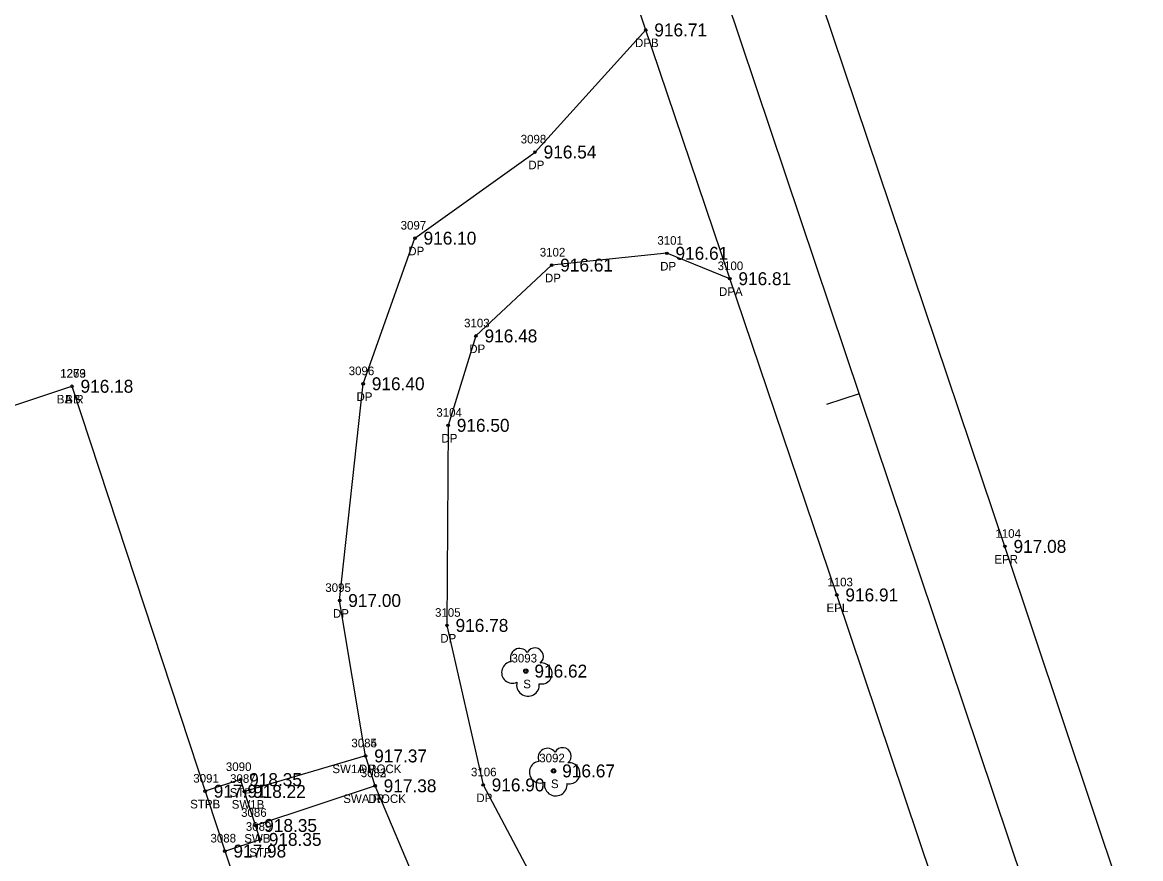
# Model space of a CAD drawing. Extents: x 1528109 to 1531398, y 1157799 to 1162548.
# Drawn here: x 1529705.3 to 1529835.3, y 1159763.8 to 1159860.9 of the extents above; entities that cross this region are included whole.
import ezdxf

# ---------------------------------------------------------------- set-up
doc = ezdxf.new("R2010")
doc.units = 0
for name, color, linetype in [('RD_EX_Bldg', 7, 'Continuous'), ('RD_EX_Bldg_txCode', 7, 'Continuous'), ('RD_EX_Conc', 7, 'Continuous'), ('RD_EX_Conc_txCode', 7, 'Continuous'), ('RD_EX_Driveway', 7, 'Continuous'), ('RD_EX_Driveway_txCode', 7, 'Continuous'), ('RD_EX_Road', 7, 'Continuous'), ('RD_EX_Road_txCode', 7, 'Continuous'), ('RD_EX_TX_Bldg_ELEV', 7, 'Continuous'), ('RD_EX_TX_Conc_ELEV', 7, 'Continuous'), ('RD_EX_TX_Driveway_ELEV', 7, 'Continuous'), ('RD_EX_TX_Road_ELEV', 7, 'Continuous'), ('RD_EX_TX_VEG_ELEV', 7, 'Continuous'), ('RD_EX_VEG', 7, 'Continuous'), ('RD_EX_VEG_txCode', 7, 'Continuous'), ('RD_HC_Cl', 7, 'Continuous'), ('RD_HC_Data_Tic', 7, 'Continuous'), ('RD_SMD_Locator', 7, 'Continuous')]:
    doc.layers.add(name, color=color, linetype=linetype)

msp = doc.modelspace()

# ---------------------------------------------------------------- linework, layer by layer
at = {"layer": 'RD_EX_Bldg'}
msp.add_lwpolyline([(1529711.08, 1159818.65), (1529739.39, 1159732.67), (1529692.67, 1159717.1), (1529664.36, 1159803.09), (1529711.08, 1159818.65)], dxfattribs=at)
at = {"layer": 'RD_EX_Conc'}
for p, q in [((1529745.23, 1159775.69), (1529731.14, 1159771.56)), ((1529746.33, 1159772.22), (1529732.44, 1159767.61))]:
    msp.add_line(p, q, dxfattribs=at)
msp.add_lwpolyline([(1529728.86, 1159764.63), (1529732.97, 1159765.99), (1529730.69, 1159772.94), (1529726.57, 1159771.59)], dxfattribs=at)
at = {"layer": 'RD_EX_Driveway'}
for points in [[(1529735.42, 1159713.63), (1529749.47, 1159720.19), (1529757.11, 1159728.54), (1529760.1, 1159739.68), (1529746.33, 1159772.22), (1529745.23, 1159775.69), (1529742.21, 1159793.75), (1529744.95, 1159818.94), (1529750.97, 1159835.86), (1529764.93, 1159845.87), (1529777.8, 1159860.06)], [(1529787.58, 1159831.15), (1529780.26, 1159834.1), (1529766.86, 1159832.73), (1529758.06, 1159824.5), (1529754.83, 1159814.11), (1529754.69, 1159790.86), (1529758.89, 1159772.32), (1529770.42, 1159750.59), (1529785.67, 1159734.66), (1529798.53, 1159731), (1529808.47, 1159733.63), (1529813.75, 1159739.88), (1529816.24, 1159746.21)]]:
    msp.add_lwpolyline(points, dxfattribs=at)
at = {"layer": 'RD_EX_Road'}
for points in [[(1530337.52, 1159156.44), (1530294.13, 1159166.93), (1530250.93, 1159177.7), (1530204.42, 1159191.5), (1530168.45, 1159204.97), (1530120.58, 1159231.54), (1530104.56, 1159243.15), (1530086.77, 1159257.61), (1530051.98, 1159290.88), (1530019.2, 1159326.18), (1529978.15, 1159378.31), (1529959.68, 1159408.2), (1529942.81, 1159442.34), (1529934.79, 1159460.88), (1529923.22, 1159491.09), (1529910.46, 1159527.95), (1529895.99, 1159570.93), (1529881.69, 1159613.98), (1529856.28, 1159690.67), (1529839.74, 1159739.71), (1529819.57, 1159800.04), (1529788.95, 1159890.99)], [(1530332.28, 1159136.67), (1530288.96, 1159147.06), (1530245.68, 1159158), (1530197.52, 1159172.18), (1530159.1, 1159186.57), (1530108.6, 1159214.89), (1530072.67, 1159242.37), (1530037.12, 1159276.96), (1530005.21, 1159311.5), (1529961.59, 1159366.88), (1529941.79, 1159398.29), (1529924.06, 1159434.11), (1529903.77, 1159484.39), (1529891.44, 1159520.8), (1529876.79, 1159564.7), (1529862.9, 1159606.82), (1529836.94, 1159684.29), (1529820.66, 1159733.09), (1529800.02, 1159794.4), (1529769.54, 1159884.46)]]:
    msp.add_lwpolyline(points, dxfattribs=at)
at = {"layer": 'RD_EX_VEG'}
for centre in [(1529763.86, 1159785.55), (1529767.09, 1159773.95)]:
    msp.add_circle(centre, 0.25, dxfattribs=at)
for centre, radius, start, end in [((1529763.14, 1159787.1), 1.08, 34.9763, 204.756), ((1529764.91, 1159787.25), 0.995, 308.7626, 152.0467), ((1529762.3, 1159785.39), 1.26, 96.4518, 294.734), ((1529765.7, 1159785.27), 1.22, 256.5667, 98.1046), ((1529764.11, 1159783.95), 1.32, 166.8827, 5.7589), ((1529766.37, 1159775.5), 1.08, 34.9763, 204.756), ((1529768.14, 1159775.66), 0.995, 308.7626, 152.0467), ((1529765.53, 1159773.8), 1.26, 96.4518, 294.734), ((1529768.93, 1159773.67), 1.22, 256.5667, 98.1046), ((1529767.34, 1159772.36), 1.32, 166.8827, 5.7589)]:
    msp.add_arc(centre, radius, start, end, dxfattribs=at)
at = {"layer": 'RD_HC_Cl'}
msp.add_line((1529913.5, 1159487.74), (1529527.85, 1160635.77), dxfattribs=at)
at = {"layer": 'RD_HC_Data_Tic'}
msp.add_line((1529802.62, 1159817.79), (1529798.83, 1159816.52), dxfattribs=at)
at = {"layer": 'RD_SMD_Locator'}
for centre in [(1529777.8, 1159860.06), (1529764.93, 1159845.87), (1529750.97, 1159835.86), (1529780.26, 1159834.1), (1529766.86, 1159832.73), (1529787.58, 1159831.15), (1529758.06, 1159824.5), (1529711.08, 1159818.65), (1529711.08, 1159818.65), (1529744.95, 1159818.94), (1529754.83, 1159814.11), (1529819.57, 1159800.04), (1529742.21, 1159793.75), (1529800.02, 1159794.4), (1529754.69, 1159790.86), (1529763.86, 1159785.55), (1529745.23, 1159775.69), (1529745.23, 1159775.69), (1529730.69, 1159772.94), (1529767.09, 1159773.95), (1529726.57, 1159771.59), (1529731.14, 1159771.56), (1529746.33, 1159772.22), (1529746.33, 1159772.22), (1529758.89, 1159772.32), (1529732.44, 1159767.61), (1529732.97, 1159765.99), (1529728.86, 1159764.63)]:
    msp.add_circle(centre, 0.15, dxfattribs=at)

# ---------------------------------------------------------------- texts
at = {"layer": 'RD_EX_Bldg_txCode'}
for s, p in [('1269', (1529709.71, 1159819.65)), ('1273', (1529709.73, 1159819.65)), ('BA R', (1529709.32, 1159816.65)), ('BB', (1529710.3, 1159816.65))]:
    msp.add_text(s, height=1, dxfattribs=at).set_placement(p)
at = {"layer": 'RD_EX_Conc_txCode'}
for s, p in [('3084', (1529743.57, 1159776.69)), ('3090', (1529728.98, 1159773.94)), ('SW1A ROCK', (1529741.37, 1159773.69)), ('3083', (1529744.66, 1159773.22)), ('3091', (1529725.19, 1159772.59)), ('3087', (1529729.47, 1159772.56)), ('STP', (1529729.42, 1159770.94)), ('STPB', (1529724.83, 1159769.59)), ('SW1B', (1529729.66, 1159769.56)), ('SWA ROCK', (1529742.63, 1159770.22)), ('3086', (1529730.75, 1159768.61)), ('3089', (1529731.3, 1159766.99)), ('3088', (1529727.19, 1159765.63)), ('SWB', (1529731.12, 1159765.61)), ('STP', (1529731.7, 1159763.99))]:
    msp.add_text(s, height=1, dxfattribs=at).set_placement(p)
at = {"layer": 'RD_EX_Driveway_txCode'}
for s, p in [('DPB', (1529776.55, 1159858.06)), ('3098', (1529763.26, 1159846.87)), ('DP', (1529764.15, 1159843.87)), ('3097', (1529749.3, 1159836.86)), ('3101', (1529779.15, 1159835.1)), ('DP', (1529750.19, 1159833.86)), ('3102', (1529765.48, 1159833.73)), ('DP', (1529779.48, 1159832.1)), ('3100', (1529786.16, 1159832.15)), ('DP', (1529766.08, 1159830.73)), ('DPA', (1529786.32, 1159829.15)), ('3103', (1529756.68, 1159825.5)), ('DP', (1529757.28, 1159822.5)), ('3096', (1529743.26, 1159819.94)), ('DP', (1529744.17, 1159816.94)), ('3104', (1529753.45, 1159815.11)), ('DP', (1529754.05, 1159812.11)), ('3095', (1529740.54, 1159794.75)), ('DP', (1529741.43, 1159791.75)), ('3105', (1529753.3, 1159791.86)), ('DP', (1529753.91, 1159788.86)), ('3085', (1529743.57, 1159776.69)), ('DP', (1529744.45, 1159773.69)), ('3082', (1529744.66, 1159773.22)), ('3106', (1529757.48, 1159773.32)), ('DP', (1529745.55, 1159770.22)), ('DP', (1529758.11, 1159770.32))]:
    msp.add_text(s, height=1, dxfattribs=at).set_placement(p)
at = {"layer": 'RD_EX_Road_txCode'}
for s, p in [('1104', (1529818.46, 1159801.04)), ('EPR', (1529818.34, 1159798.04)), ('1103', (1529798.92, 1159795.4)), ('EPL', (1529798.82, 1159792.4))]:
    msp.add_text(s, height=1, dxfattribs=at).set_placement(p)
at = {"layer": 'RD_EX_TX_Bldg_ELEV'}
msp.add_text('916.18', height=1.5, dxfattribs=at).set_placement((1529712.08, 1159817.9))
msp.add_text('916.18', height=1.5, dxfattribs=at).set_placement((1529712.08, 1159817.9))
at = {"layer": 'RD_EX_TX_Conc_ELEV'}
for s, p in [('917.37', (1529746.23, 1159774.94)), ('918.35', (1529731.69, 1159772.19)), ('917.38', (1529747.33, 1159771.47)), ('917.91', (1529727.57, 1159770.84)), ('918.22', (1529732.14, 1159770.81)), ('918.35', (1529733.44, 1159766.86)), ('918.35', (1529733.97, 1159765.24)), ('917.98', (1529729.86, 1159763.88))]:
    msp.add_text(s, height=1.5, dxfattribs=at).set_placement(p)
at = {"layer": 'RD_EX_TX_Driveway_ELEV'}
for s, p in [('916.71', (1529778.8, 1159859.31)), ('916.54', (1529765.93, 1159845.12)), ('916.10', (1529751.97, 1159835.11)), ('916.61', (1529781.26, 1159833.35)), ('916.61', (1529767.86, 1159831.98)), ('916.81', (1529788.58, 1159830.4)), ('916.48', (1529759.06, 1159823.75)), ('916.40', (1529745.95, 1159818.19)), ('916.50', (1529755.83, 1159813.36)), ('917.00', (1529743.21, 1159793)), ('916.78', (1529755.69, 1159790.11)), ('917.37', (1529746.23, 1159774.94)), ('917.38', (1529747.33, 1159771.47)), ('916.90', (1529759.89, 1159771.57))]:
    msp.add_text(s, height=1.5, dxfattribs=at).set_placement(p)
at = {"layer": 'RD_EX_TX_Road_ELEV'}
for s, p in [('917.08', (1529820.57, 1159799.29)), ('916.91', (1529801.02, 1159793.65))]:
    msp.add_text(s, height=1.5, dxfattribs=at).set_placement(p)
at = {"layer": 'RD_EX_TX_VEG_ELEV'}
for s, p in [('916.62', (1529764.86, 1159784.8)), ('916.67', (1529768.09, 1159773.2))]:
    msp.add_text(s, height=1.5, dxfattribs=at).set_placement(p)
at = {"layer": 'RD_EX_VEG_txCode'}
for s, p in [('3093', (1529762.19, 1159786.55)), ('S', (1529763.56, 1159783.55)), ('3092', (1529765.42, 1159774.95)), ('S', (1529766.78, 1159771.95))]:
    msp.add_text(s, height=1, dxfattribs=at).set_placement(p)

doc.saveas('drawing.dxf')
